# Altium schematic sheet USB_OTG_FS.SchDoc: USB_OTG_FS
size A4; Date: Not used; ApprovedBy: Not used; CheckedBy: Not used; Author: Not used; CompanyName: STMicroelectronics; DrawnBy: Not used; Engineer: Not used; Organization: Not used; Address1: Not used; Address2: Not used; Address3: Not used; Address4: Not used; DocumentNumber: Not used; Revision: Not used; SheetNumber: 5; SheetTotal: 23
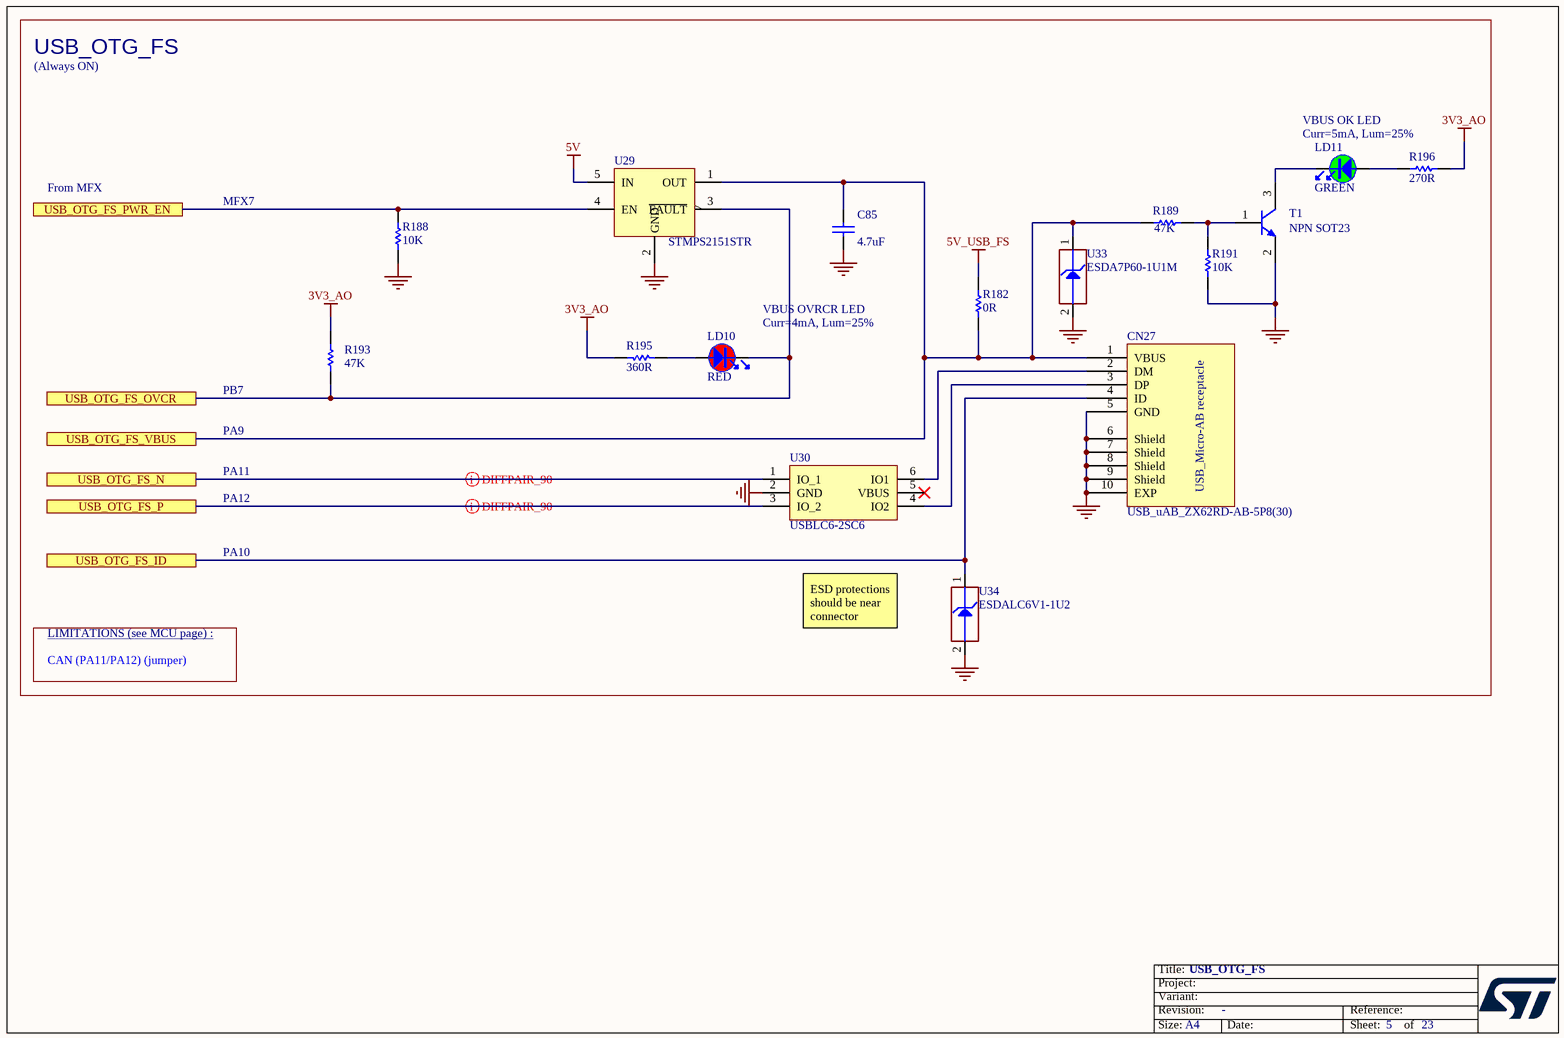
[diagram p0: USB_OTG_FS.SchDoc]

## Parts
C85  value 4.7uF  [C0603]  (hidden comment: Capacitor)
CN27  value USB_uAB_ZX62RD-AB-5P8(30)  [CON_USBMICROAB_MOLEX_47590-0001_H3]  (hidden comment: USB_uAB_47590.0001)
LD10  value RED  [LED_0603_VISHAY_VLMS1300-GS08_RED_1A2K_H0P8]  (hidden comment: LED_red)
LD11  value GREEN  [LED_0603_OSRAM_LG-Q396-PS-35_GREEN_1A2K_H0P4]  (hidden comment: LED_green)
R182  value 0R  [R0805]  (hidden comment: Resistor)
R188  value 10K  [R0402]  (hidden comment: Resistor)
R189  value 47K  [R0402]  (hidden comment: Resistor)
R191  value 10K  [R0402]  (hidden comment: Resistor)
R193  value 47K  [R0402]  (hidden comment: Resistor)
R195  value 360R  [R0402]  (hidden comment: Resistor)
R196  value 270R  [R0402]  (hidden comment: Resistor)
T1  value NPN SOT23  [NPN_SOT23]  (hidden comment: 9013-SOT23)
U29  STMPS2151STR  [MOS_SOT23-5L]
U30  USBLC6-2SC6  [ESD_SOT23-6L]
U33  value ESDA7P60-1U1M  [ESD_QFN2_1P6X1_P125]  (hidden comment: ESD-TRANSIL)
U34  value ESDALC6V1-1U2  [ESD_ST0201]  (hidden comment: ESD-TRANSIL)

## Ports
USB_OTG_FS_ID, USB_OTG_FS_N, USB_OTG_FS_OVCR, USB_OTG_FS_P, USB_OTG_FS_PWR_EN, USB_OTG_FS_VBUS

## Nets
3V3_AO: R193.2 R195.2 R196.2
5V: U29.5(IN)
5V_USB_FS: R182.2
GND: C85.1 CN27.5(GND) CN27.6(Shield) CN27.7(Shield) CN27.8(Shield) CN27.9(Shield) CN27.10(EXP) R188.2 R191.1 T1.2(E) U29.2(GND) U30.2(GND) U33.2(GND) U34.2(GND)
USB_OTG_FS_ID: CN27.4(ID) U34.1(IO1) ; port USB_OTG_FS_ID
USB_OTG_FS_N: U30.1(IO_1) ; port USB_OTG_FS_N
USB_OTG_FS_OVCR: LD10.2 R193.1 U29.3(~{FAULT}) ; port USB_OTG_FS_OVCR
USB_OTG_FS_P: U30.3(IO_2) ; port USB_OTG_FS_P
USB_OTG_FS_PWR_EN: R188.1 U29.4(EN) ; port USB_OTG_FS_PWR_EN
USB_OTG_FS_VBUS: C85.2 CN27.1(VBUS) R182.1 R189.1 U29.1(OUT) U33.1(IO1) ; port USB_OTG_FS_VBUS
NetCN27_2: CN27.2(DM) U30.6(IO1)
NetCN27_3: CN27.3(DP) U30.4(IO2)
NetLD10_1: LD10.1 R195.1
NetLD11_1: LD11.1 R196.1
NetLD11_2: LD11.2 T1.3(C)
NetR189_2: R189.2 R191.2 T1.1(B)

Not connected (* = marked no-connect by the designer): U30 5(VBUS)*

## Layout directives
differential pair: USB_OTG_FS_N, USB_OTG_FS_P

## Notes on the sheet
- USB_OTG_FS
- (Always ON)
- VBUS OK LED
- Curr=5mA, Lum=25%
- From MFX
- MFX7
- VBUS OVRCR LED
- Curr=4mA, Lum=25%
- PA9
- PB7
- PA11
- PA12
- PA10
- LIMITATIONS (see MCU page) :
- ESD protections should be near connector
- CAN (PA11/PA12) (jumper)

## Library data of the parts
C85 = MCD-00009: Capacitor, MLCC, 4.7uF, 16V, X5R, 10%, 0603, T=0.8mm; Manufacturer_Part_Number: CC0603KRX5R7BB475; Manufacturer: YAGEO; Part_Preference: Recommended; Partial_Alternate_Internal_Part_Number: MCD-03565; Provided_By: SUBCO; ECCN_US: EAR99; ECCN_EU: NEC; Alternate_EMS: A; Component_Country_Of_Origin: China; ID: 2471; ShowFields: YES
CN27 = MCD-00661: USB-MICRO-AB Receptacle, RA, SMT + DIP, Standard, Top Mount, USB certified (symbol & footprint compatible with MCD-00022); Part_Type: Connector; Manufacturer_Part_Number: ZX62RD-AB-5P8(30); Manufacturer: HIROSE; Part_Preference: Recommended; Provided_By: SUBCO; Component_Country_Of_Origin: Japan; ID: 3083; Order_Code_RS: 136-1404; ShowFields: YES
LD10 = MCD-00587: LED Red, 0603 SMD, 2V Forward Voltage; Part_Type: Display; Manufacturer_Part_Number: VLMS1300-GS08; Manufacturer: VISHAY; Alternate_Manufacturer_Part_Number: LS Q976-NR-1; Alternate_Manufacturer: OSRAM OPTO SEMICONDUCTORS; Full_Alternate_Internal_Part_Number: MCD-02401; Part_Preference: Recommended; Provided_By: SUBCO; Component_Country_Of_Origin: China; ID: 3154; ShowFields: YES
LD11 = MCD-00588: LED Green, 0603 SMD, Forward Voltage Typ=2V, Max=2.5V; Part_Type: Display; Manufacturer_Part_Number: LG Q396-PS-35; Manufacturer: OSRAM OPTO SEMICONDUCTORS; Alternate_Manufacturer_Part_Number: VLMTG1300-GS08; Alternate_Manufacturer: VISHAY SEMICONDUCTOR OPTO DIVISION; Part_Preference: Recommended; Partial_Alternate_Internal_Part_Number: MCD-02400, MCD-03155; Provided_By: SUBCO; Component_Country_Of_Origin: Unknown; ID: 3155; ShowFields: YES
R182 = MCD-00179: Resistor,0R,0805,5%; Manufacturer_Part_Number: RC0805JR-070RL; Manufacturer: YAGEO; Part_Preference: Recommended; Provided_By: SUBCO; ECCN_US: EAR99; ECCN_EU: NEC; Component_Country_Of_Origin: China; ID: 2685; ShowFields: YES
R188 R191 = MCD-00053: Resistor,10K,0402,1%,1/16W; Manufacturer_Part_Number: RC0402FR-0710KL; Manufacturer: YAGEO; BMS_Part_Number: 9131590; Part_Preference: Recommended; Provided_By: SUBCO; ECCN_US: EAR99; ECCN_EU: NEC; Component_Country_Of_Origin: China; ID: 2539; Order_Code_RS: 9239359; ShowFields: YES
R189 R193 = MCD-00063: Resistor,47K,0402,1%,1/16W; Manufacturer_Part_Number: RC0402FR-0747KL; Manufacturer: YAGEO; Part_Preference: Recommended; Provided_By: SUBCO; ECCN_US: EAR99; ECCN_EU: NEC; Component_Country_Of_Origin: China; ID: 2528; Order_Code_RS: 9239430; ShowFields: YES
R195 = MCD-00461: Resistor,360R,0402,1%,1/16W; Manufacturer_Part_Number: RC0402FR-07360RL; Manufacturer: YAGEO; Part_Preference: Recommended; Provided_By: SUBCO; ECCN_US: EAR99; ECCN_EU: NEC; Component_Country_Of_Origin: China; ID: 2816; ShowFields: YES
R196 = MCD-00441: Resistor,270R,0402,1%,1/16W; Manufacturer_Part_Number: RC0402FR-07270RL; Manufacturer: YAGEO; Part_Preference: Recommended; Provided_By: SUBCO; ECCN_US: EAR99; ECCN_EU: NEC; Component_Country_Of_Origin: China; ID: 2838; ShowFields: YES
T1 = MCD-00073: NPN Bipolar Transistor; Manufacturer_Part_Number: BSR14; Manufacturer: ON SEMICONDUCTOR; Part_Type: IC; Alternate_Manufacturer_Part_Number: MMBT2222LT1G / MMBT2222ALT1G / MMBT2222ALT3G; Part_Preference: Recommended; Partial_Alternate_Internal_Part_Number: MCD-01737, MCD-03305, , MCD-02988; Provided_By: SUBCO; ECCN_US: EAR99; ECCN_EU: NEC; Component_Country_Of_Origin: Unknown; ID: 2519; ShowFields: YES
U29 = MCD-00159: 500mA, Enhanced single channel power switches with active high enable pin; Manufacturer: STMICROELECTRONICS; Part_Type: IC; Alternate_Manufacturer_Part_Number: TPS2051C; Alternate_Manufacturer: TEXAS INSTRUMENTS; BMS_Part_Number: 9159009; Part_Preference: Recommended; Provided_By: SUBCO with ST control; ECCN_US: EAR99; ECCN_EU: NEC; Component_Country_Of_Origin: Malaysia; ID: 2708; Order_Code_RS: 165-5516; ShowFields: YES
U30 = MCD-00163: Very low capacitance ESD protection; Part_Type: Diode; Manufacturer: STMICROELECTRONICS; BMS_Part_Number: 9151075; Part_Preference: Recommended; Provided_By: SUBCO with ST control; ECCN_US: EAR99; ECCN_EU: NEC; Component_Country_Of_Origin: China; ID: 2707; Order_Code_RS: 920-6266; ShowFields: YES
U33 = MCD-00251: High power transient voltage suppressor, 7V breakdown; Part_Type: Diode; Manufacturer: STMICROELECTRONICS; BMS_Part_Number: 9179042; Manufacturer_HQ_COO: EU; Part_Preference: Recommended; Provided_By: SUBCO with ST control; ECCN_US: EAR99; ECCN_EU: NEC; Component_Country_Of_Origin: China; ID: 2618; Order_Code_RS: 110-6381; ShowFields: YES
U34 = MCD-00170: ESD protection 6V1; Part_Type: Diode; Manufacturer: STMICROELECTRONICS; BMS_Part_Number: 9151132; Manufacturer_HQ_COO: EU; Part_Preference: Recommended; Provided_By: SUBCO with ST control; ECCN_US: EAR99; ECCN_EU: NEC; Component_Country_Of_Origin: China; ID: 2696; Order_Code_RS: 795-8404; ShowFields: YES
